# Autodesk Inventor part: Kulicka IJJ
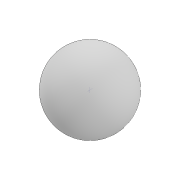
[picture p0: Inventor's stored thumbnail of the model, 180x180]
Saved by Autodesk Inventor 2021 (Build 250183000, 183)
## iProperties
Created: 2023-12
Part Number: Kulicka IJJ
Material: Všeobecné
Document SubType Name: Modeling
Designer: tatulinek
Density: 1 g/cm^3
Appearance: Výchozí
Author: tatulinek
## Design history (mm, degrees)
sketch "Náčrt1"
  geometry: L1 (-4.5, 0)-(4.5, 0); A1 r 4.5 centre (0, 0) between (-4.5, 0) and (4.5, 0); 2 further points
  constraints: 2 coincident, 2 end point, 2 point on circle, 1 centre point, 1 horizontal, 1 midpoint
  dimensions: "d0" = 9 diameter of A1
revolve "Rotace1" sketch "Náčrt1" stored, may be unused: angle "d1" = 90 deg
sketch "Náčrt2"
  geometry: 2 further points
  constraints: 1 coincident
node "Těleso1"
